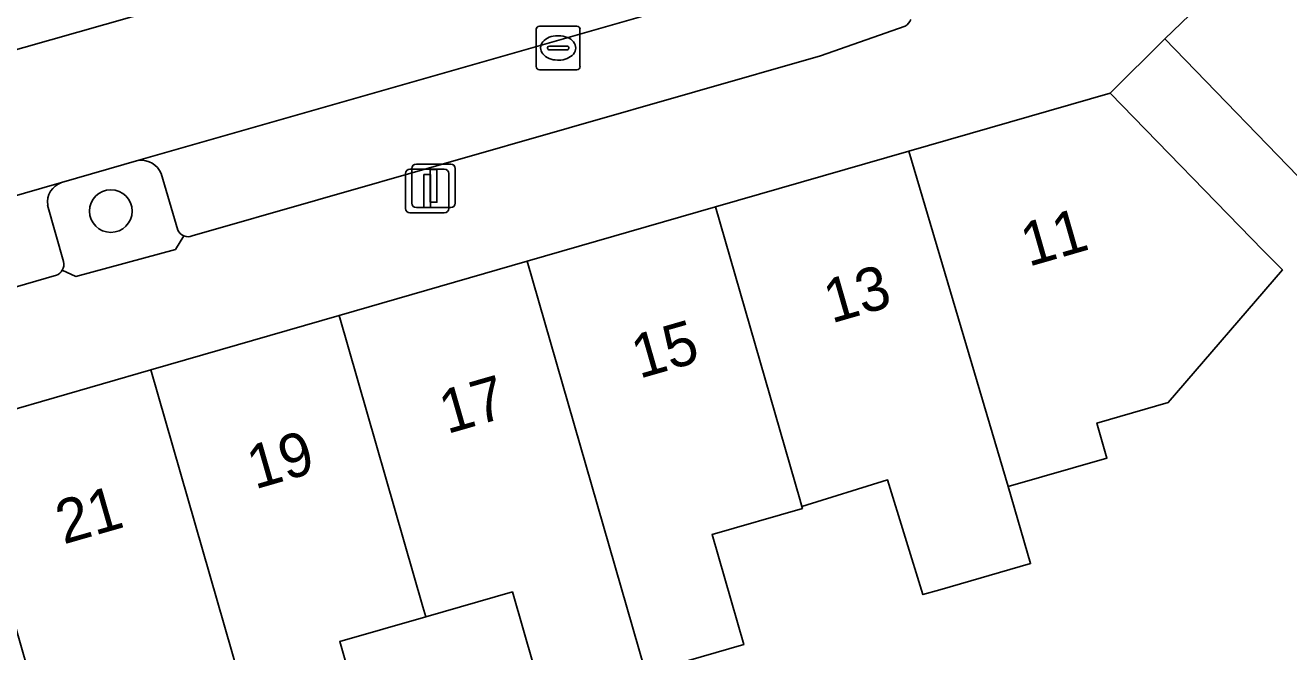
# Model space of a CAD drawing. Extents: x 159716 to 160783, y 383290 to 384031.
# Drawn here: x 160344.3 to 160373.24, y 383590.97 to 383605.32 of the extents above; entities that cross this region are included whole.
import ezdxf

# ---------------------------------------------------------------- set-up
doc = ezdxf.new("R2010")
doc.units = 0
for name, color, linetype in [('IMGEO_Boom', 7, 'Continuous'), ('IMGEO_Erf', 7, 'Continuous'), ('IMGEO_Groenvoorziening', 7, 'Continuous'), ('IMGEO_Kolk', 7, 'Continuous'), ('IMGEO_Lichtmast', 7, 'Continuous'), ('IMGEO_Pand', 7, 'Continuous'), ('IMGEO_Pand_nummerreeks', 7, 'Continuous'), ('IMGEO_Parkeervlak_open', 7, 'Continuous'), ('IMGEO_Rijbaan_lokaal_open', 7, 'Continuous'), ('IMGEO_Voetpad_open', 7, 'Continuous')]:
    doc.layers.add(name, color=color, linetype=linetype)

msp = doc.modelspace()

# ---------------------------------------------------------------- linework, layer by layer
at = {"layer": 'IMGEO_Boom'}
msp.add_circle((160346.26, 383601.066), 0.489, dxfattribs=at)
at = {"layer": 'IMGEO_Erf'}
for points in [[(160373.926, 383601.377), (160370.406, 383605.011), (160369.15, 383603.77), (160372.66, 383600.16), (160373.097, 383599.718), (160370.483, 383596.679), (160368.848, 383596.209), (160369.079, 383595.406), (160366.819, 383594.755), (160367.328, 383592.988), (160365.248, 383592.39), (160364.863, 383592.279), (160364.054, 383594.904), (160362.088, 383594.298), (160362.101, 383594.253), (160360.033, 383593.658), (160360.76, 383591.131), (160358.514, 383590.485)], [(160356.186, 383589.815), (160355.46, 383592.34), (160353.475, 383591.769), (160351.505, 383591.202), (160352.225, 383588.7)]]:
    msp.add_lwpolyline(points, dxfattribs=at)
at = {"layer": 'IMGEO_Groenvoorziening'}
for points in [[(160346.901, 383602.229), (160345.132, 383601.719)], [(160347.791, 383600.63), (160347.413, 383601.928)], [(160344.812, 383601.202), (160345.177, 383599.907)], [(160345.148, 383599.709), (160345.456, 383599.57), (160347.739, 383600.182), (160347.935, 383600.496)]]:
    msp.add_lwpolyline(points, dxfattribs=at)
for centre, radius, start, end in [((160346.943, 383601.714), 0.517, 24.4842, 94.6141), ((160345.283, 383601.268), 0.475, 108.4756, 188.0131), ((160348.029, 383600.741), 0.263, 205.0743, 249.0459), ((160344.907, 383599.845), 0.276, 330.4513, 12.8836)]:
    msp.add_arc(centre, radius, start, end, dxfattribs=at)
at = {"layer": 'IMGEO_Kolk'}
for p, q in [((160356.081, 383605.304), (160356.933, 383605.304)), ((160356.006, 383604.378), (160356.006, 383605.23)), ((160356.494, 383605.084), (160356.519, 383605.084)), ((160357.007, 383605.23), (160357.007, 383604.378)), ((160356.265, 383604.798), (160356.265, 383604.81)), ((160356.703, 383604.761), (160356.305, 383604.761)), ((160356.308, 383604.847), (160356.706, 383604.847)), ((160356.749, 383604.81), (160356.749, 383604.798)), ((160356.517, 383604.524), (160356.492, 383604.524)), ((160356.933, 383604.304), (160356.081, 383604.304))]:
    msp.add_line(p, q, dxfattribs=at)
for points in [[(160356.081, 383605.304), (160356.933, 383605.304)], [(160356.006, 383604.378), (160356.006, 383605.23)], [(160357.007, 383605.23), (160357.007, 383604.378)], [(160356.933, 383604.304), (160356.081, 383604.304)]]:
    msp.add_lwpolyline(points, dxfattribs=at)
for centre, radius, start, end in [((160356.083, 383605.228), 0.0765, 91.552, 178.448), ((160356.083, 383605.228), 0.0765, 91.552, 178.448), ((160356.931, 383605.228), 0.0765, 1.552, 88.448), ((160356.931, 383605.228), 0.0765, 1.552, 88.448), ((160356.305, 383604.807), 0.0403, 85.8775, 175.7526), ((160356.302, 383604.797), 0.0366, 178.938, 274.7102), ((160356.706, 383604.804), 0.043, 264.8664, 352.4533), ((160356.71, 383604.809), 0.0386, 1.7309, 96.639), ((160356.083, 383604.38), 0.0765, 181.552, 268.448), ((160356.083, 383604.38), 0.0765, 181.552, 268.448), ((160356.931, 383604.38), 0.0765, 271.552, 358.448), ((160356.931, 383604.38), 0.0765, 271.552, 358.448)]:
    msp.add_arc(centre, radius, start, end, dxfattribs=at)
for centre, major_axis, ratio, start_param, end_param in [((160356.493, 383604.804), (-0.387, 0.002), 0.722429, 4.712389, 7.853982), ((160356.518, 383604.804), (-0.39, 0.002), 0.717154, 1.570796, 4.712389)]:
    msp.add_ellipse(centre, major_axis=major_axis, ratio=ratio, start_param=start_param, end_param=end_param, dxfattribs=at)
at = {"layer": 'IMGEO_Lichtmast'}
for p, q in [((160353.258, 383602.144), (160354.048, 383602.144)), ((160354.048, 383602.144), (160353.258, 383602.144)), ((160353.009, 383601.125), (160353.009, 383601.925)), ((160353.009, 383601.925), (160353.009, 383601.125)), ((160353.109, 383602.025), (160353.899, 383602.025)), ((160353.899, 383602.025), (160353.109, 383602.025)), ((160353.158, 383601.244), (160353.158, 383602.044)), ((160353.158, 383602.044), (160353.158, 383601.244)), ((160353.999, 383601.925), (160353.999, 383601.125)), ((160353.999, 383601.125), (160353.999, 383601.925)), ((160354.148, 383602.044), (160354.148, 383601.244)), ((160354.148, 383601.244), (160354.148, 383602.044)), ((160353.899, 383601.025), (160353.109, 383601.025)), ((160353.109, 383601.025), (160353.899, 383601.025)), ((160354.048, 383601.144), (160353.258, 383601.144)), ((160353.258, 383601.144), (160354.048, 383601.144))]:
    msp.add_line(p, q, dxfattribs=at)
for points in [[(160353.429, 383601.9), (160353.579, 383601.9), (160353.579, 383601.15), (160353.429, 383601.15), (160353.429, 383601.9)], [(160353.578, 383602.019), (160353.728, 383602.019), (160353.728, 383601.269), (160353.578, 383601.269), (160353.578, 383602.019)]]:
    msp.add_lwpolyline(points, dxfattribs=at)
for centre, start, end in [((160353.258, 383602.044), 90, 180), ((160353.258, 383602.044), 90, 180), ((160354.048, 383602.044), 0, 90), ((160354.048, 383602.044), 360, 90), ((160353.109, 383601.925), 90, 180), ((160353.109, 383601.925), 90, 180), ((160353.899, 383601.925), 0, 90), ((160353.899, 383601.925), 360, 90), ((160353.258, 383601.244), 180, 270), ((160353.258, 383601.244), 180, 270), ((160354.048, 383601.244), 270, 0), ((160354.048, 383601.244), 270, 0), ((160353.109, 383601.125), 180, 270), ((160353.109, 383601.125), 180, 270), ((160353.899, 383601.125), 270, 0), ((160353.899, 383601.125), 270, 0)]:
    msp.add_arc(centre, 0.1, start, end, dxfattribs=at)
at = {"layer": 'IMGEO_Pand'}
for points in [[(160380.575, 383602.456), (160374.378, 383608.83), (160370.406, 383605.011), (160373.926, 383601.377), (160376.63, 383598.596), (160378.318, 383600.238), (160382.49, 383595.911), (160384.759, 383598.117)], [(160372.66, 383600.16), (160369.15, 383603.77), (160364.538, 383602.439), (160366.819, 383594.755), (160369.079, 383595.406), (160368.848, 383596.209), (160370.483, 383596.679), (160373.097, 383599.718)], [(160364.538, 383602.439), (160360.113, 383601.162), (160362.041, 383594.461), (160362.088, 383594.298), (160364.054, 383594.904), (160364.863, 383592.279), (160365.248, 383592.39), (160367.328, 383592.988), (160366.819, 383594.755)], [(160360.113, 383601.162), (160355.8, 383599.916), (160358.486, 383590.583), (160358.514, 383590.485), (160360.76, 383591.131), (160360.033, 383593.658), (160362.101, 383594.253), (160362.088, 383594.298), (160362.041, 383594.461)], [(160355.8, 383599.916), (160351.488, 383598.672), (160353.409, 383591.999), (160353.475, 383591.769), (160355.46, 383592.34), (160356.186, 383589.815), (160358.514, 383590.485), (160358.486, 383590.583)], [(160351.488, 383598.672), (160347.175, 383597.427), (160349.881, 383588.026), (160352.225, 383588.7), (160351.505, 383591.202), (160353.475, 383591.769), (160353.409, 383591.999)], [(160347.175, 383597.427), (160342.737, 383596.145), (160344.134, 383591.334), (160344.733, 383589.253), (160346.812, 383589.851), (160347.532, 383587.35), (160349.881, 383588.026)]]:
    msp.add_lwpolyline(points, close=True, dxfattribs=at)
at = {"layer": 'IMGEO_Parkeervlak_open'}
for points in [[(160278.849, 383586.224), (160280.889, 383586.747), (160286.571, 383588.273), (160316.301, 383596.829), (160319.597, 383597.777), (160328.281, 383600.276), (160360.238, 383609.357)], [(160361.709, 383606.473), (160346.901, 383602.229)], [(160348.125, 383600.497), (160362.518, 383604.626), (160364.459, 383605.305)], [(160347.413, 383601.928), (160347.791, 383600.63)], [(160345.132, 383601.719), (160327.401, 383596.608)], [(160345.177, 383599.907), (160344.812, 383601.202)], [(160328.613, 383594.837), (160345.017, 383599.594)]]:
    msp.add_lwpolyline(points, dxfattribs=at)
for centre, radius, start, end in [((160364.292, 383605.577), 0.32, 301.6016, 337.1321), ((160346.943, 383601.714), 0.517, 24.4842, 94.6141), ((160345.283, 383601.268), 0.475, 108.4756, 188.0131), ((160348.029, 383600.741), 0.263, 205.0743, 249.0459), ((160348.029, 383600.746), 0.267, 249.4272, 291.176), ((160344.907, 383599.845), 0.276, 330.4513, 12.8836), ((160344.91, 383599.848), 0.275, 292.8251, 329.7322)]:
    msp.add_arc(centre, radius, start, end, dxfattribs=at)
at = {"layer": 'IMGEO_Rijbaan_lokaal_open'}
msp.add_lwpolyline([(160360.238, 383609.357), (160328.281, 383600.276), (160319.597, 383597.777), (160320.503, 383594.602), (160325.619, 383596.076), (160327.401, 383596.608), (160345.132, 383601.719), (160346.901, 383602.229), (160361.709, 383606.473)], dxfattribs=at)
at = {"layer": 'IMGEO_Voetpad_open'}
for points in [[(160342.737, 383596.145), (160347.175, 383597.427), (160351.488, 383598.672), (160355.8, 383599.916), (160360.113, 383601.162), (160364.538, 383602.439), (160369.15, 383603.77), (160370.406, 383605.011), (160374.378, 383608.83), (160378.272, 383612.574), (160382.166, 383616.317), (160386.061, 383620.061), (160390.014, 383623.862)], [(160364.459, 383605.305), (160362.518, 383604.626), (160348.125, 383600.497)], [(160347.935, 383600.496), (160347.739, 383600.182), (160345.456, 383599.57), (160345.148, 383599.709)], [(160345.017, 383599.594), (160328.613, 383594.837)]]:
    msp.add_lwpolyline(points, dxfattribs=at)
for centre, radius, start, end in [((160364.292, 383605.577), 0.32, 301.6016, 337.1321), ((160348.029, 383600.746), 0.267, 249.4272, 291.176), ((160344.91, 383599.848), 0.275, 292.8251, 329.7322)]:
    msp.add_arc(centre, radius, start, end, dxfattribs=at)

# ---------------------------------------------------------------- texts
at = {"layer": 'IMGEO_Pand_nummerreeks'}
for s, p in [('11', (160367.283, 383599.786)), ('13', (160362.77, 383598.488)), ('15', (160358.366, 383597.22)), ('17', (160353.962, 383595.953)), ('19', (160349.559, 383594.685)), ('21', (160345.176, 383593.424))]:
    msp.add_text(s, height=1, rotation=16.06, dxfattribs=at).set_placement(p)

doc.saveas('drawing.dxf')
